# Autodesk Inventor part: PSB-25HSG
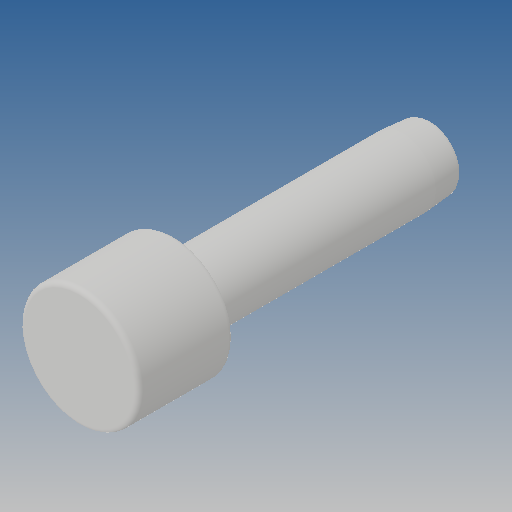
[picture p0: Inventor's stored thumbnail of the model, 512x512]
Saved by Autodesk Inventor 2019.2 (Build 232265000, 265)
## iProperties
Created: 2010-02
Part Number: PSB-25HSG
Material: Ogólny
Document SubType Name: Modeling
Designer: CADENGINEERING4
Density: 1 g/cm^3
Appearance: Domyślna
Author: CADENGINEERING4
Revision Number: 1LAST_VERSION
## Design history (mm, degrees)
feature "Baza1"
node "Bryła1"
